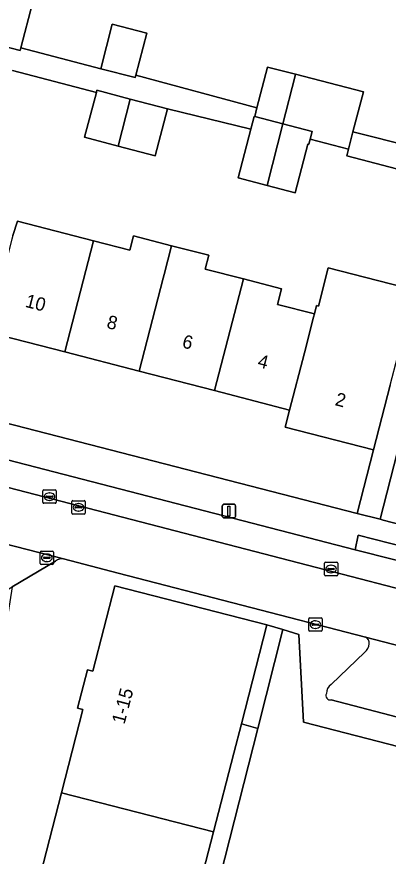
# Model space of a CAD drawing. Extents: x 163683 to 164494, y 382709 to 383872.
# Drawn here: x 164132.9 to 164160.7, y 383122.3 to 383185.1 of the extents above; entities that cross this region are included whole.
import ezdxf

# ---------------------------------------------------------------- set-up
doc = ezdxf.new("R2010")
doc.units = 0
for name, color, linetype in [('IMGEO_Erf', 7, 'Continuous'), ('IMGEO_Groenvoorziening', 7, 'Continuous'), ('IMGEO_Kolk', 7, 'Continuous'), ('IMGEO_Lichtmast', 7, 'Continuous'), ('IMGEO_Pand', 7, 'Continuous'), ('IMGEO_Pand_nummerreeks', 7, 'Continuous'), ('IMGEO_Parkeervlak_open', 7, 'Continuous'), ('IMGEO_Rijbaan_lokaal_open', 7, 'Continuous'), ('IMGEO_Rioolput', 7, 'Continuous'), ('IMGEO_Voetpad_op_trap', 7, 'Continuous'), ('IMGEO_Voetpad_open', 7, 'Continuous')]:
    doc.layers.add(name, color=color, linetype=linetype)

msp = doc.modelspace()

# ---------------------------------------------------------------- linework, layer by layer
at = {"layer": 'IMGEO_Erf'}
for points in [[(164134.054, 383186.11), (164133.188, 383182.758), (164139.159, 383181.203), (164140.027, 383184.533), (164142.605, 383183.861), (164141.783, 383180.711), (164150.841, 383178.278), (164151.631, 383181.327), (164153.73, 383180.783), (164158.793, 383179.47), (164158.018, 383176.482), (164162.462, 383175.349)], [(164161.835, 383173.554), (164157.549, 383174.672), (164157.684, 383175.191), (164154.814, 383175.935), (164154.714, 383175.551), (164154.651, 383175.567), (164153.708, 383171.927), (164151.609, 383172.471), (164149.434, 383173.035), (164150.374, 383176.667), (164144.147, 383178.21), (164143.23, 383174.694), (164140.455, 383175.418), (164137.958, 383176.069), (164138.832, 383179.422), (164132.558, 383181.059)], [(164132.583, 383168.714), (164132.93, 383169.785), (164138.622, 383168.313), (164141.324, 383167.614), (164141.605, 383168.701), (164144.459, 383167.962), (164147.232, 383167.244), (164146.965, 383166.213), (164149.824, 383165.473), (164152.678, 383164.735), (164152.377, 383163.573), (164155.139, 383162.858), (164155.299, 383163.476), (164155.43, 383163.442), (164156.172, 383166.308), (164162.663, 383164.627)], [(164161.326, 383152.458), (164160.047, 383147.491), (164160.268, 383147.434), (164163.748, 383146.536)]]:
    msp.add_lwpolyline(points, dxfattribs=at)
msp.add_lwpolyline([(164142.036, 383158.573), (164136.48, 383160.01), (164130.721, 383161.5), (164125.256, 383162.914), (164119.425, 383164.422), (164119.606, 383165.12), (164116.548, 383165.912), (164114.798, 383159.148), (164118.294, 383158.243), (164158.327, 383147.934), (164159.549, 383152.678), (164152.953, 383154.385), (164153.284, 383155.663), (164147.668, 383157.116)], close=True, dxfattribs=at)
at = {"layer": 'IMGEO_Groenvoorziening'}
msp.add_lwpolyline([(164176.537, 383126.569), (164154.315, 383132.306), (164153.975, 383138.872), (164152.776, 383139.237), (164150.9, 383131.848), (164147.04, 383116.646), (164145.764, 383116.973), (164145.551, 383116.143), (164148.108, 383115.477), (164150.025, 383115.042), (164150.47, 383114.883), (164148.895, 383108.547), (164170.385, 383102.927)], close=True, dxfattribs=at)
at = {"layer": 'IMGEO_Kolk'}
for p, q in [((164134.833, 383148.763), (164134.833, 383149.615)), ((164134.908, 383149.689), (164135.76, 383149.689)), ((164135.092, 383149.183), (164135.092, 383149.195)), ((164135.135, 383149.232), (164135.533, 383149.232)), ((164135.321, 383149.469), (164135.346, 383149.469)), ((164135.576, 383149.195), (164135.576, 383149.183)), ((164135.834, 383149.615), (164135.834, 383148.763)), ((164135.76, 383148.689), (164134.908, 383148.689)), ((164135.53, 383149.146), (164135.132, 383149.146)), ((164135.344, 383148.909), (164135.319, 383148.909)), ((164134.629, 383144.188), (164134.629, 383145.04)), ((164134.704, 383145.114), (164135.556, 383145.114)), ((164135.117, 383144.894), (164135.142, 383144.894)), ((164135.63, 383145.04), (164135.63, 383144.188)), ((164134.888, 383144.608), (164134.888, 383144.62)), ((164135.326, 383144.571), (164134.928, 383144.571)), ((164134.931, 383144.657), (164135.329, 383144.657)), ((164135.14, 383144.334), (164135.115, 383144.334)), ((164135.372, 383144.62), (164135.372, 383144.608)), ((164155.879, 383143.348), (164155.879, 383144.2)), ((164155.954, 383144.274), (164156.806, 383144.274)), ((164156.88, 383144.2), (164156.88, 383143.348)), ((164135.556, 383144.114), (164134.704, 383144.114)), ((164156.138, 383143.768), (164156.138, 383143.78)), ((164156.576, 383143.731), (164156.178, 383143.731)), ((164156.181, 383143.817), (164156.579, 383143.817)), ((164156.367, 383144.054), (164156.392, 383144.054)), ((164156.622, 383143.78), (164156.622, 383143.768)), ((164156.806, 383143.274), (164155.954, 383143.274)), ((164156.39, 383143.494), (164156.365, 383143.494)), ((164154.706, 383139.188), (164154.706, 383140.04)), ((164154.781, 383140.114), (164155.633, 383140.114)), ((164155.194, 383139.894), (164155.219, 383139.894)), ((164155.707, 383140.04), (164155.707, 383139.188)), ((164154.965, 383139.608), (164154.965, 383139.62)), ((164155.403, 383139.571), (164155.005, 383139.571)), ((164155.008, 383139.657), (164155.406, 383139.657)), ((164155.217, 383139.334), (164155.192, 383139.334)), ((164155.449, 383139.62), (164155.449, 383139.608)), ((164155.633, 383139.114), (164154.781, 383139.114))]:
    msp.add_line(p, q, dxfattribs=at)
for points in [[(164134.833, 383148.763), (164134.833, 383149.615)], [(164134.908, 383149.689), (164135.76, 383149.689)], [(164135.834, 383149.615), (164135.834, 383148.763)], [(164135.76, 383148.689), (164134.908, 383148.689)], [(164134.629, 383144.188), (164134.629, 383145.04)], [(164134.704, 383145.114), (164135.556, 383145.114)], [(164135.63, 383145.04), (164135.63, 383144.188)], [(164155.879, 383143.348), (164155.879, 383144.2)], [(164155.954, 383144.274), (164156.806, 383144.274)], [(164156.88, 383144.2), (164156.88, 383143.348)], [(164135.556, 383144.114), (164134.704, 383144.114)], [(164156.806, 383143.274), (164155.954, 383143.274)], [(164154.706, 383139.188), (164154.706, 383140.04)], [(164154.781, 383140.114), (164155.633, 383140.114)], [(164155.707, 383140.04), (164155.707, 383139.188)], [(164155.633, 383139.114), (164154.781, 383139.114)]]:
    msp.add_lwpolyline(points, dxfattribs=at)
for centre, radius, start, end in [((164134.91, 383149.613), 0.0765, 91.55205, 178.44795), ((164134.91, 383149.613), 0.0765, 91.55205, 178.44795), ((164135.132, 383149.192), 0.0403, 85.87752, 175.75265), ((164135.537, 383149.194), 0.0386, 1.73085, 96.63898), ((164135.758, 383149.613), 0.0765, 1.55205, 88.44795), ((164135.758, 383149.613), 0.0765, 1.55205, 88.44795), ((164134.91, 383148.765), 0.0765, 181.55205, 268.44795), ((164134.91, 383148.765), 0.0765, 181.55205, 268.44795), ((164135.129, 383149.182), 0.0366, 178.93798, 274.71019), ((164135.533, 383149.189), 0.043, 264.86636, 352.45326), ((164135.758, 383148.765), 0.0765, 271.55205, 358.44795), ((164135.758, 383148.765), 0.0765, 271.55205, 358.44795), ((164134.706, 383145.038), 0.0765, 91.55205, 178.44795), ((164134.706, 383145.038), 0.0765, 91.55205, 178.44795), ((164135.554, 383145.038), 0.0765, 1.55205, 88.44795), ((164135.554, 383145.038), 0.0765, 1.55205, 88.44795), ((164134.706, 383144.19), 0.0765, 181.55205, 268.44795), ((164134.706, 383144.19), 0.0765, 181.55205, 268.44795), ((164134.928, 383144.617), 0.0403, 85.87752, 175.75265), ((164134.925, 383144.607), 0.0366, 178.93798, 274.71019), ((164135.329, 383144.614), 0.043, 264.86636, 352.45326), ((164135.333, 383144.619), 0.0386, 1.73085, 96.63898), ((164135.554, 383144.19), 0.0765, 271.55205, 358.44795), ((164135.554, 383144.19), 0.0765, 271.55205, 358.44795), ((164155.956, 383144.198), 0.0765, 91.55205, 178.44795), ((164155.956, 383144.198), 0.0765, 91.55205, 178.44795), ((164156.804, 383144.198), 0.0765, 1.55205, 88.44795), ((164156.804, 383144.198), 0.0765, 1.55205, 88.44795), ((164156.178, 383143.777), 0.0403, 85.87752, 175.75265), ((164156.175, 383143.767), 0.0366, 178.93798, 274.71019), ((164156.579, 383143.774), 0.043, 264.86636, 352.45326), ((164156.583, 383143.779), 0.0386, 1.73085, 96.63898), ((164155.956, 383143.35), 0.0765, 181.55205, 268.44795), ((164155.956, 383143.35), 0.0765, 181.55205, 268.44795), ((164156.804, 383143.35), 0.0765, 271.55205, 358.44795), ((164156.804, 383143.35), 0.0765, 271.55205, 358.44795), ((164154.783, 383140.038), 0.0765, 91.55205, 178.44795), ((164154.783, 383140.038), 0.0765, 91.55205, 178.44795), ((164155.631, 383140.038), 0.0765, 1.55205, 88.44795), ((164155.631, 383140.038), 0.0765, 1.55205, 88.44795), ((164154.783, 383139.19), 0.0765, 181.55205, 268.44795), ((164154.783, 383139.19), 0.0765, 181.55205, 268.44795), ((164155.005, 383139.617), 0.0403, 85.87752, 175.75265), ((164155.002, 383139.607), 0.0366, 178.93798, 274.71019), ((164155.406, 383139.614), 0.043, 264.86636, 352.45326), ((164155.41, 383139.619), 0.0386, 1.73085, 96.63898), ((164155.631, 383139.19), 0.0765, 271.55205, 358.44795), ((164155.631, 383139.19), 0.0765, 271.55205, 358.44795)]:
    msp.add_arc(centre, radius, start, end, dxfattribs=at)
for centre, major_axis, ratio, start_param, end_param in [((164135.32, 383149.189), (-0.387, 0.002), 0.722429, 4.712389, 7.853982), ((164135.345, 383149.189), (-0.39, 0.002), 0.717154, 1.570796, 4.712389), ((164135.116, 383144.614), (-0.387, 0.002), 0.722429, 4.712389, 7.853982), ((164135.141, 383144.614), (-0.39, 0.002), 0.717154, 1.570796, 4.712389), ((164156.366, 383143.774), (-0.387, 0.002), 0.722429, 4.712389, 7.853982), ((164156.391, 383143.774), (-0.39, 0.002), 0.717154, 1.570796, 4.712389), ((164155.193, 383139.614), (-0.387, 0.002), 0.722429, 4.712389, 7.853982), ((164155.218, 383139.614), (-0.39, 0.002), 0.717154, 1.570796, 4.712389)]:
    msp.add_ellipse(centre, major_axis=major_axis, ratio=ratio, start_param=start_param, end_param=end_param, dxfattribs=at)
at = {"layer": 'IMGEO_Lichtmast'}
for p, q in [((164148.349, 383148.612), (164149.139, 383148.612)), ((164149.139, 383148.612), (164148.349, 383148.612)), ((164148.249, 383147.712), (164148.249, 383148.512)), ((164148.249, 383148.512), (164148.249, 383147.712)), ((164149.239, 383148.512), (164149.239, 383147.712)), ((164149.239, 383147.712), (164149.239, 383148.512)), ((164149.139, 383147.612), (164148.349, 383147.612)), ((164148.349, 383147.612), (164149.139, 383147.612))]:
    msp.add_line(p, q, dxfattribs=at)
msp.add_lwpolyline([(164148.669, 383148.487), (164148.819, 383148.487), (164148.819, 383147.737), (164148.669, 383147.737), (164148.669, 383148.487)], dxfattribs=at)
for centre, start, end in [((164148.349, 383148.512), 90, 180), ((164148.349, 383148.512), 90, 180), ((164149.139, 383148.512), 0, 90), ((164149.139, 383148.512), 360, 90), ((164148.349, 383147.712), 180, 270), ((164148.349, 383147.712), 180, 270), ((164149.139, 383147.712), 270, 0), ((164149.139, 383147.712), 270, 0)]:
    msp.add_arc(centre, 0.1, start, end, dxfattribs=at)
at = {"layer": 'IMGEO_Pand'}
for points in [[(164131.343, 383186.81), (164130.425, 383183.253), (164133.135, 383182.553), (164133.188, 383182.758), (164134.054, 383186.11)], [(164142.605, 383183.861), (164140.027, 383184.533), (164139.159, 383181.203), (164141.736, 383180.531), (164141.783, 383180.711)], [(164153.7, 383180.666), (164153.73, 383180.783), (164151.631, 383181.327), (164150.841, 383178.278), (164150.669, 383177.616), (164152.782, 383177.069)], [(164158.793, 383179.47), (164153.73, 383180.783), (164153.7, 383180.666), (164152.782, 383177.069), (164154.961, 383176.504), (164154.814, 383175.935), (164157.684, 383175.191), (164158.018, 383176.482)], [(164141.372, 383178.934), (164138.875, 383179.586), (164138.832, 383179.422), (164137.958, 383176.069), (164140.455, 383175.418)], [(164144.147, 383178.21), (164141.372, 383178.934), (164140.455, 383175.418), (164143.23, 383174.694)], [(164152.782, 383177.069), (164150.669, 383177.616), (164150.623, 383177.628), (164150.374, 383176.667), (164149.434, 383173.035), (164151.609, 383172.471)], [(164154.651, 383175.567), (164154.714, 383175.551), (164154.814, 383175.935), (164154.961, 383176.504), (164152.782, 383177.069), (164151.609, 383172.471), (164153.708, 383171.927)], [(164138.622, 383168.313), (164132.93, 383169.785), (164132.583, 383168.714), (164132.516, 383168.457), (164130.721, 383161.5), (164136.48, 383160.01)], [(164142.036, 383158.573), (164143.833, 383165.537), (164143.901, 383165.802), (164144.459, 383167.962), (164141.605, 383168.701), (164141.324, 383167.614), (164138.622, 383168.313), (164136.48, 383160.01)], [(164142.036, 383158.573), (164147.668, 383157.116), (164149.824, 383165.473), (164146.965, 383166.213), (164147.232, 383167.244), (164144.459, 383167.962), (164143.901, 383165.802), (164143.833, 383165.537)], [(164161.368, 383159.71), (164161.9, 383161.767), (164162.663, 383164.627), (164156.172, 383166.308), (164155.43, 383163.442), (164155.299, 383163.476), (164155.139, 383162.858), (164155.077, 383162.617), (164154.387, 383159.942), (164153.284, 383155.663), (164152.953, 383154.385), (164159.549, 383152.678), (164160.801, 383157.519)], [(164155.139, 383162.858), (164152.377, 383163.573), (164152.678, 383164.735), (164149.824, 383165.473), (164147.668, 383157.116), (164153.284, 383155.663), (164154.387, 383159.942), (164155.077, 383162.617)], [(164136.228, 383127.03), (164147.597, 383124.11), (164149.112, 383130.005), (164149.674, 383132.195), (164151.577, 383139.602), (164140.215, 383142.52), (164138.574, 383136.131), (164138.165, 383136.237), (164137.427, 383133.367), (164137.829, 383133.264)], [(164146.083, 383118.215), (164147.597, 383124.11), (164136.228, 383127.03), (164134.658, 383120.919), (164134.287, 383121.015), (164133.546, 383118.131), (164133.897, 383118.041), (164132.278, 383111.736), (164143.667, 383108.811), (164145.551, 383116.143), (164145.764, 383116.973)]]:
    msp.add_lwpolyline(points, close=True, dxfattribs=at)
at = {"layer": 'IMGEO_Parkeervlak_open'}
for points in [[(164174.26, 383141.034), (164164.014, 383143.739), (164158.179, 383145.198), (164118.793, 383155.404), (164107.839, 383158.274), (164097.462, 383160.961), (164079.713, 383165.583), (164070.239, 383167.953), (164061.314, 383170.172), (164056.554, 383171.505), (164053.618, 383172.103), (164052.199, 383172.252)], [(164055.386, 383169.723), (164107.356, 383156.336), (164176.893, 383138.284)], [(164136.378, 383144.539), (164119.374, 383148.903)], [(164130.197, 383141.044), (164132.544, 383142.44), (164135.788, 383144.369)], [(164176.052, 383134.239), (164158.955, 383138.686)], [(164158.899, 383137.562), (164156.376, 383135.143)], [(164156.384, 383133.974), (164168.976, 383130.685)]]:
    msp.add_lwpolyline(points, dxfattribs=at)
for centre, radius, start, end in [((164136.317, 383143.643), 0.898, 86.07808, 126.06907), ((164158.762, 383138.256), 0.471, 349.55946, 65.77405), ((164158.461, 383138.188), 0.764, 304.96212, 358.71726), ((164156.888, 383134.453), 0.859, 126.58933, 179.67992), ((164156.337, 383134.312), 0.341, 154.57325, 277.94468)]:
    msp.add_arc(centre, radius, start, end, dxfattribs=at)
at = {"layer": 'IMGEO_Rijbaan_lokaal_open'}
msp.add_lwpolyline([(164051.953, 383166.18), (164055.133, 383165.53), (164056.663, 383165.132), (164070.595, 383161.529), (164076.984, 383159.809), (164094.778, 383155.262), (164095.995, 383154.966), (164119.374, 383148.903), (164136.378, 383144.539), (164140.46, 383143.471), (164158.955, 383138.686), (164176.052, 383134.239), (164177.133, 383138.238), (164176.893, 383138.284), (164107.356, 383156.336), (164055.386, 383169.723)], dxfattribs=at)
at = {"layer": 'IMGEO_Rioolput'}
for p, q in [((164137.001, 383147.96), (164137.001, 383148.812)), ((164137.076, 383148.886), (164137.928, 383148.886)), ((164137.489, 383148.666), (164137.514, 383148.666)), ((164138.002, 383148.812), (164138.002, 383147.96)), ((164137.26, 383148.38), (164137.26, 383148.392)), ((164137.698, 383148.343), (164137.3, 383148.343)), ((164137.303, 383148.429), (164137.701, 383148.429)), ((164137.512, 383148.106), (164137.487, 383148.106)), ((164137.744, 383148.392), (164137.744, 383148.38)), ((164137.928, 383147.886), (164137.076, 383147.886))]:
    msp.add_line(p, q, dxfattribs=at)
for points in [[(164137.001, 383147.96), (164137.001, 383148.812)], [(164137.076, 383148.886), (164137.928, 383148.886)], [(164138.002, 383148.812), (164138.002, 383147.96)], [(164137.928, 383147.886), (164137.076, 383147.886)]]:
    msp.add_lwpolyline(points, dxfattribs=at)
for centre, radius, start, end in [((164137.078, 383148.81), 0.0765, 91.55205, 178.44795), ((164137.078, 383148.81), 0.0765, 91.55205, 178.44795), ((164137.926, 383148.81), 0.0765, 1.55205, 88.44795), ((164137.926, 383148.81), 0.0765, 1.55205, 88.44795), ((164137.078, 383147.962), 0.0765, 181.55205, 268.44795), ((164137.078, 383147.962), 0.0765, 181.55205, 268.44795), ((164137.3, 383148.389), 0.0403, 85.87752, 175.75265), ((164137.297, 383148.379), 0.0366, 178.93798, 274.71019), ((164137.701, 383148.386), 0.043, 264.86636, 352.45326), ((164137.705, 383148.391), 0.0386, 1.73085, 96.63898), ((164137.926, 383147.962), 0.0765, 271.55205, 358.44795), ((164137.926, 383147.962), 0.0765, 271.55205, 358.44795)]:
    msp.add_arc(centre, radius, start, end, dxfattribs=at)
for centre, major_axis, ratio, start_param, end_param in [((164137.488, 383148.386), (-0.387, 0.002), 0.722429, 4.712389, 7.853982), ((164137.513, 383148.386), (-0.39, 0.002), 0.717154, 1.570796, 4.712389)]:
    msp.add_ellipse(centre, major_axis=major_axis, ratio=ratio, start_param=start_param, end_param=end_param, dxfattribs=at)
at = {"layer": 'IMGEO_Voetpad_op_trap'}
msp.add_lwpolyline([(164152.776, 383139.237), (164151.577, 383139.602), (164149.674, 383132.195), (164150.9, 383131.848)], close=True, dxfattribs=at)
at = {"layer": 'IMGEO_Voetpad_open'}
for points in [[(164132.558, 383181.059), (164138.832, 383179.422), (164138.875, 383179.586), (164141.372, 383178.934), (164144.147, 383178.21), (164150.374, 383176.667), (164150.623, 383177.628), (164150.669, 383177.616), (164150.841, 383178.278), (164141.783, 383180.711), (164141.736, 383180.531), (164139.159, 383181.203), (164133.188, 383182.758), (164133.135, 383182.553), (164130.425, 383183.253)], [(164162.462, 383175.349), (164158.018, 383176.482), (164157.684, 383175.191), (164157.549, 383174.672), (164161.835, 383173.554)], [(164052.199, 383172.252), (164053.618, 383172.103), (164056.554, 383171.505), (164061.314, 383170.172), (164061.645, 383171.365), (164070.479, 383169.093), (164070.239, 383167.953), (164079.713, 383165.583), (164097.462, 383160.961), (164107.839, 383158.274), (164108.137, 383159.36), (164119.093, 383156.434), (164118.793, 383155.404), (164158.179, 383145.198), (164158.404, 383146.3), (164164.26, 383144.799), (164164.014, 383143.739), (164174.26, 383141.034)], [(164176.893, 383138.284), (164177.133, 383138.238), (164178.77, 383142.588), (164163.748, 383146.536), (164160.268, 383147.434), (164160.047, 383147.491), (164158.327, 383147.934), (164118.294, 383158.243)], [(164160.801, 383157.519), (164159.549, 383152.678), (164158.327, 383147.934), (164160.047, 383147.491), (164161.326, 383152.458)], [(164135.788, 383144.369), (164132.544, 383142.44), (164131.864, 383138.13), (164131.674, 383136.743), (164127.676, 383113.511)], [(164158.955, 383138.686), (164140.46, 383143.471), (164136.378, 383144.539)], [(164134.658, 383120.919), (164136.228, 383127.03), (164137.829, 383133.264), (164137.427, 383133.367), (164138.165, 383136.237), (164138.574, 383136.131), (164140.215, 383142.52), (164151.577, 383139.602), (164152.776, 383139.237), (164153.975, 383138.872), (164154.315, 383132.306), (164176.537, 383126.569), (164179.925, 383127.281), (164180.219, 383128.415)], [(164156.376, 383135.143), (164158.899, 383137.562)], [(164168.976, 383130.685), (164156.384, 383133.974)]]:
    msp.add_lwpolyline(points, dxfattribs=at)
for points in [[(164164.014, 383143.739), (164164.26, 383144.799), (164158.404, 383146.3), (164158.179, 383145.198)], [(164150.9, 383131.848), (164149.674, 383132.195), (164149.112, 383130.005), (164147.597, 383124.11), (164146.083, 383118.215), (164145.764, 383116.973), (164147.04, 383116.646)]]:
    msp.add_lwpolyline(points, close=True, dxfattribs=at)
for centre, radius, start, end in [((164136.317, 383143.643), 0.898, 86.07808, 126.06907), ((164158.762, 383138.256), 0.471, 349.55946, 65.77405), ((164158.461, 383138.188), 0.764, 304.96212, 358.71726), ((164156.888, 383134.453), 0.859, 126.58933, 179.67992), ((164156.337, 383134.312), 0.341, 154.57325, 277.94468)]:
    msp.add_arc(centre, radius, start, end, dxfattribs=at)

# ---------------------------------------------------------------- texts
at = {"layer": 'IMGEO_Pand_nummerreeks'}
for s, rotation, p in [('10', 345.49608, (164133.455, 383163.396)), ('8', 345.49608, (164139.544, 383161.82)), ('6', 345.49608, (164145.184, 383160.361)), ('4', 345.49844, (164150.827, 383158.9)), ('2', 345.49271, (164156.614, 383156.04)), ('1-15', 75.29756, (164140.934, 383132.114))]:
    msp.add_text(s, height=1, rotation=rotation, dxfattribs=at).set_placement(p)

doc.saveas('drawing.dxf')
